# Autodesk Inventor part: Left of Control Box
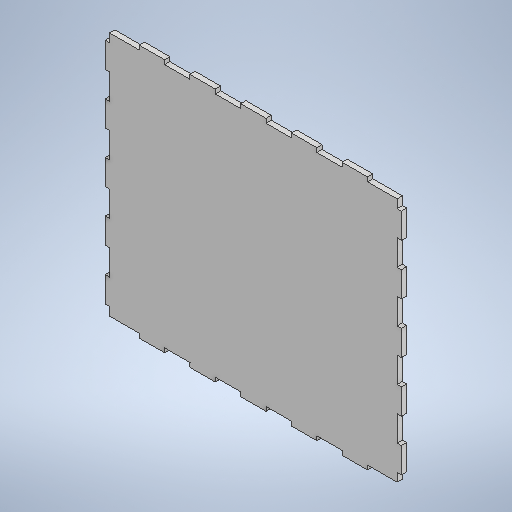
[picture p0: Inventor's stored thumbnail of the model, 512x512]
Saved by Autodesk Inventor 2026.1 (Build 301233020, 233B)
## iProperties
Created: 2026-11
Part Number: Left of Control Box
Material: Generic
Document SubType Name: Modeling
Designer: hp
Density: 1 g/cm^3
Appearance: Default
Author: hp
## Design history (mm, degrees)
sketch "Sketch1"
  geometry: L1 (104, 4)-(104, 0); L2 (104, 4)-(104, 0); L3 (104, 0)-(80, 0); L4 (80, 0)-(80, 4); L5 (104, 0)-(80, 0); L6 (80, 0)-(80, 4); L7 (80, 4)-(104, 4); L8 (80, 4)-(104, 4); L9 (128, 0)-(128, 4); L10 (128, 0)-(128, 4); L11 (152, 0)-(128, 0); L12 (128, 4)-(152, 4); L13 (152, 0)-(128, 0); L14 (128, 4)-(152, 4); L15 (152, 4)-(152, 0); L16 (0, 240)-(280, 240); L17 (280, 240)-(280, 0); L18 (280, 0)-(0, 0); L19 (0, 0)-(0, 240); L20 (56, 4)-(56, 0); L21 (56, 0)-(32, 0); L22 (32, 0)-(32, 4); L23 (32, 4)-(56, 4); L24 (140, 240)-(140, 0); L25 (280, 120)-(0, 120); L26 (176, 0)-(176, 4); L27 (176, 0)-(176, 4); L28 (200, 0)-(176, 0); L29 (200, 0)-(176, 0); L30 (176, 4)-(200, 4); L31 (200, 4)-(200, 0); L32 (224, 0)-(224, 4); L33 (248, 4)-(248, 0); L34 (224, 4)-(248, 4); L35 (248, 0)-(224, 0); L36 (152, 4)-(152, 0); L37 (128, 240)-(128, 236); L38 (128, 240)-(128, 236); L39 (128, 240)-(128, 236); L40 (128, 236)-(152, 236); L41 (128, 236)-(152, 236); L42 (152, 240)-(128, 240); L43 (152, 240)-(128, 240); L44 (152, 236)-(152, 240); L45 (152, 236)-(152, 240); L46 (200, 236)-(200, 240); L47 (176, 240)-(176, 236); L48 (176, 240)-(176, 236); L49 (200, 240)-(176, 240); L50 (176, 236)-(200, 236); L51 (200, 240)-(176, 240); L52 (176, 236)-(200, 236); L53 (200, 236)-(200, 240); L54 (224, 240)-(224, 236); L55 (224, 236)-(248, 236); L56 (248, 240)-(224, 240); L57 (248, 236)-(248, 240); L58 (176, 4)-(200, 4); L59 (200, 4)-(200, 0); L60 (152, 4)-(152, 0); L61 (128, 0)-(128, 4); L62 (152, 0)-(128, 0); L63 (128, 4)-(152, 4); L64 (80, 240)-(80, 236)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; 113 further points
  constraints: 308 end point, 90 symmetric about line, 8 parallel, 6 midpoint, 5 horizontal, 4 perpendicular, 2 vertical, 1 point on line, 3 other
  dimensions: "d14" = 280 distance of L17.end L18.end; "d15" = 240 distance of L16.end L17.end; "d16" = 24 distance of L9.end L12.end; "d17" = 4 distance of L9.start L9.end; "d18" = 48 distance of L11.start L1.end; "d19" = 48 distance of L11.start L28.start; "d20" = 4 distance of L97.end L96.end; "d21" = 24 distance of L96.end L95.end; "d22" = 48 distance of L95.end L83.end; "d23" = 48 distance of L95.end L107.end; "d24" = 4 distance between parallel lines of L16 L151
extrude "Extrusion2" new body sketch "Sketch1" distance "d25" = 5; taper "d26" = 0 deg
body "Solid2"
node "Sketch Rectangular Pattern2" dims "d18" = 48, "d19" = 48
node "Sketch Rectangular Pattern4" dims "d22" = 48, "d23" = 48
